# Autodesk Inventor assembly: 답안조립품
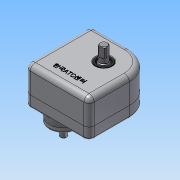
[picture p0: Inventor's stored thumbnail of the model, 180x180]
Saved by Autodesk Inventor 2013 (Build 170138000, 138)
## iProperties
Created: 2015-11
Part Number: 답안조립품
Document SubType Name: Assembly
Designer: Administrator
Author: Administrator
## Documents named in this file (13)
- C:\Users\Administrator\Desktop\Inventor2급-김민서\2급\공용부품_20151104_2\답안조립품.iam
- C:\Users\Administrator\Desktop\Inventor2급-김민서\2급\공용부품_20151104_2\본체.ipt
- C:\Users\Administrator\Desktop\Inventor2급-김민서\2급\공용부품_20151104_2\M3 x 0.5.ipt
- C:\Users\Administrator\Desktop\Inventor2급-김민서\2급\공용부품_20151104_2\M4 x 0.7.ipt
- C:\Users\Administrator\Desktop\Inventor2급-김민서\2급\공용부품_20151104_2\로드 축.ipt
- C:\Users\Administrator\Desktop\Inventor2급-김민서\2급\공용부품_20151104_2\로드.ipt
- C:\Users\Administrator\Desktop\Inventor2급-김민서\2급\공용부품_20151104_2\베어링 6001.ipt
- C:\Users\Administrator\Desktop\Inventor2급-김민서\2급\공용부품_20151104_2\베어링 6002.ipt
- C:\Users\Administrator\Desktop\Inventor2급-김민서\2급\공용부품_20151104_2\앞커버.ipt
- C:\Users\Administrator\Desktop\Inventor2급-김민서\2급\공용부품_20151104_2\오일실 12 x 22.ipt
- C:\Users\Administrator\Desktop\Inventor2급-김민서\2급\공용부품_20151104_2\오일실 15 x 25.ipt
- C:\Users\Administrator\Desktop\Inventor2급-김민서\2급\공용부품_20151104_2\축 커버.ipt
- C:\Users\Administrator\Desktop\Inventor2급-김민서\2급\공용부품_20151104_2\편심 축.ipt
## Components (9 placed, 2 different names)
1. M4 x 0.7:1
2. M4 x 0.7:2
3. M4 x 0.7:3
4. M4 x 0.7:5
5. M4 x 0.7:6
6. M3 x 0.5:1
7. M3 x 0.5:2
8. M3 x 0.5:3
9. M3 x 0.5:4
